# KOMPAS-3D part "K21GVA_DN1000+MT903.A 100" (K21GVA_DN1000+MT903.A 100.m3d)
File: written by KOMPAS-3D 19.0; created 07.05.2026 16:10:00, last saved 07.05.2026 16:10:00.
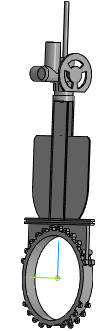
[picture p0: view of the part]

Document properties: Автор: Энергия; Полное имя файла: ..\K21GVA_DN50-DN1000+MT903.A\K21GVA_DN1000+MT903.A 100.a3d

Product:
- Part/product: K21GVA_DN1000+MT903.A 100
    Масса: 873.943

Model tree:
1. Операция без истории:1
